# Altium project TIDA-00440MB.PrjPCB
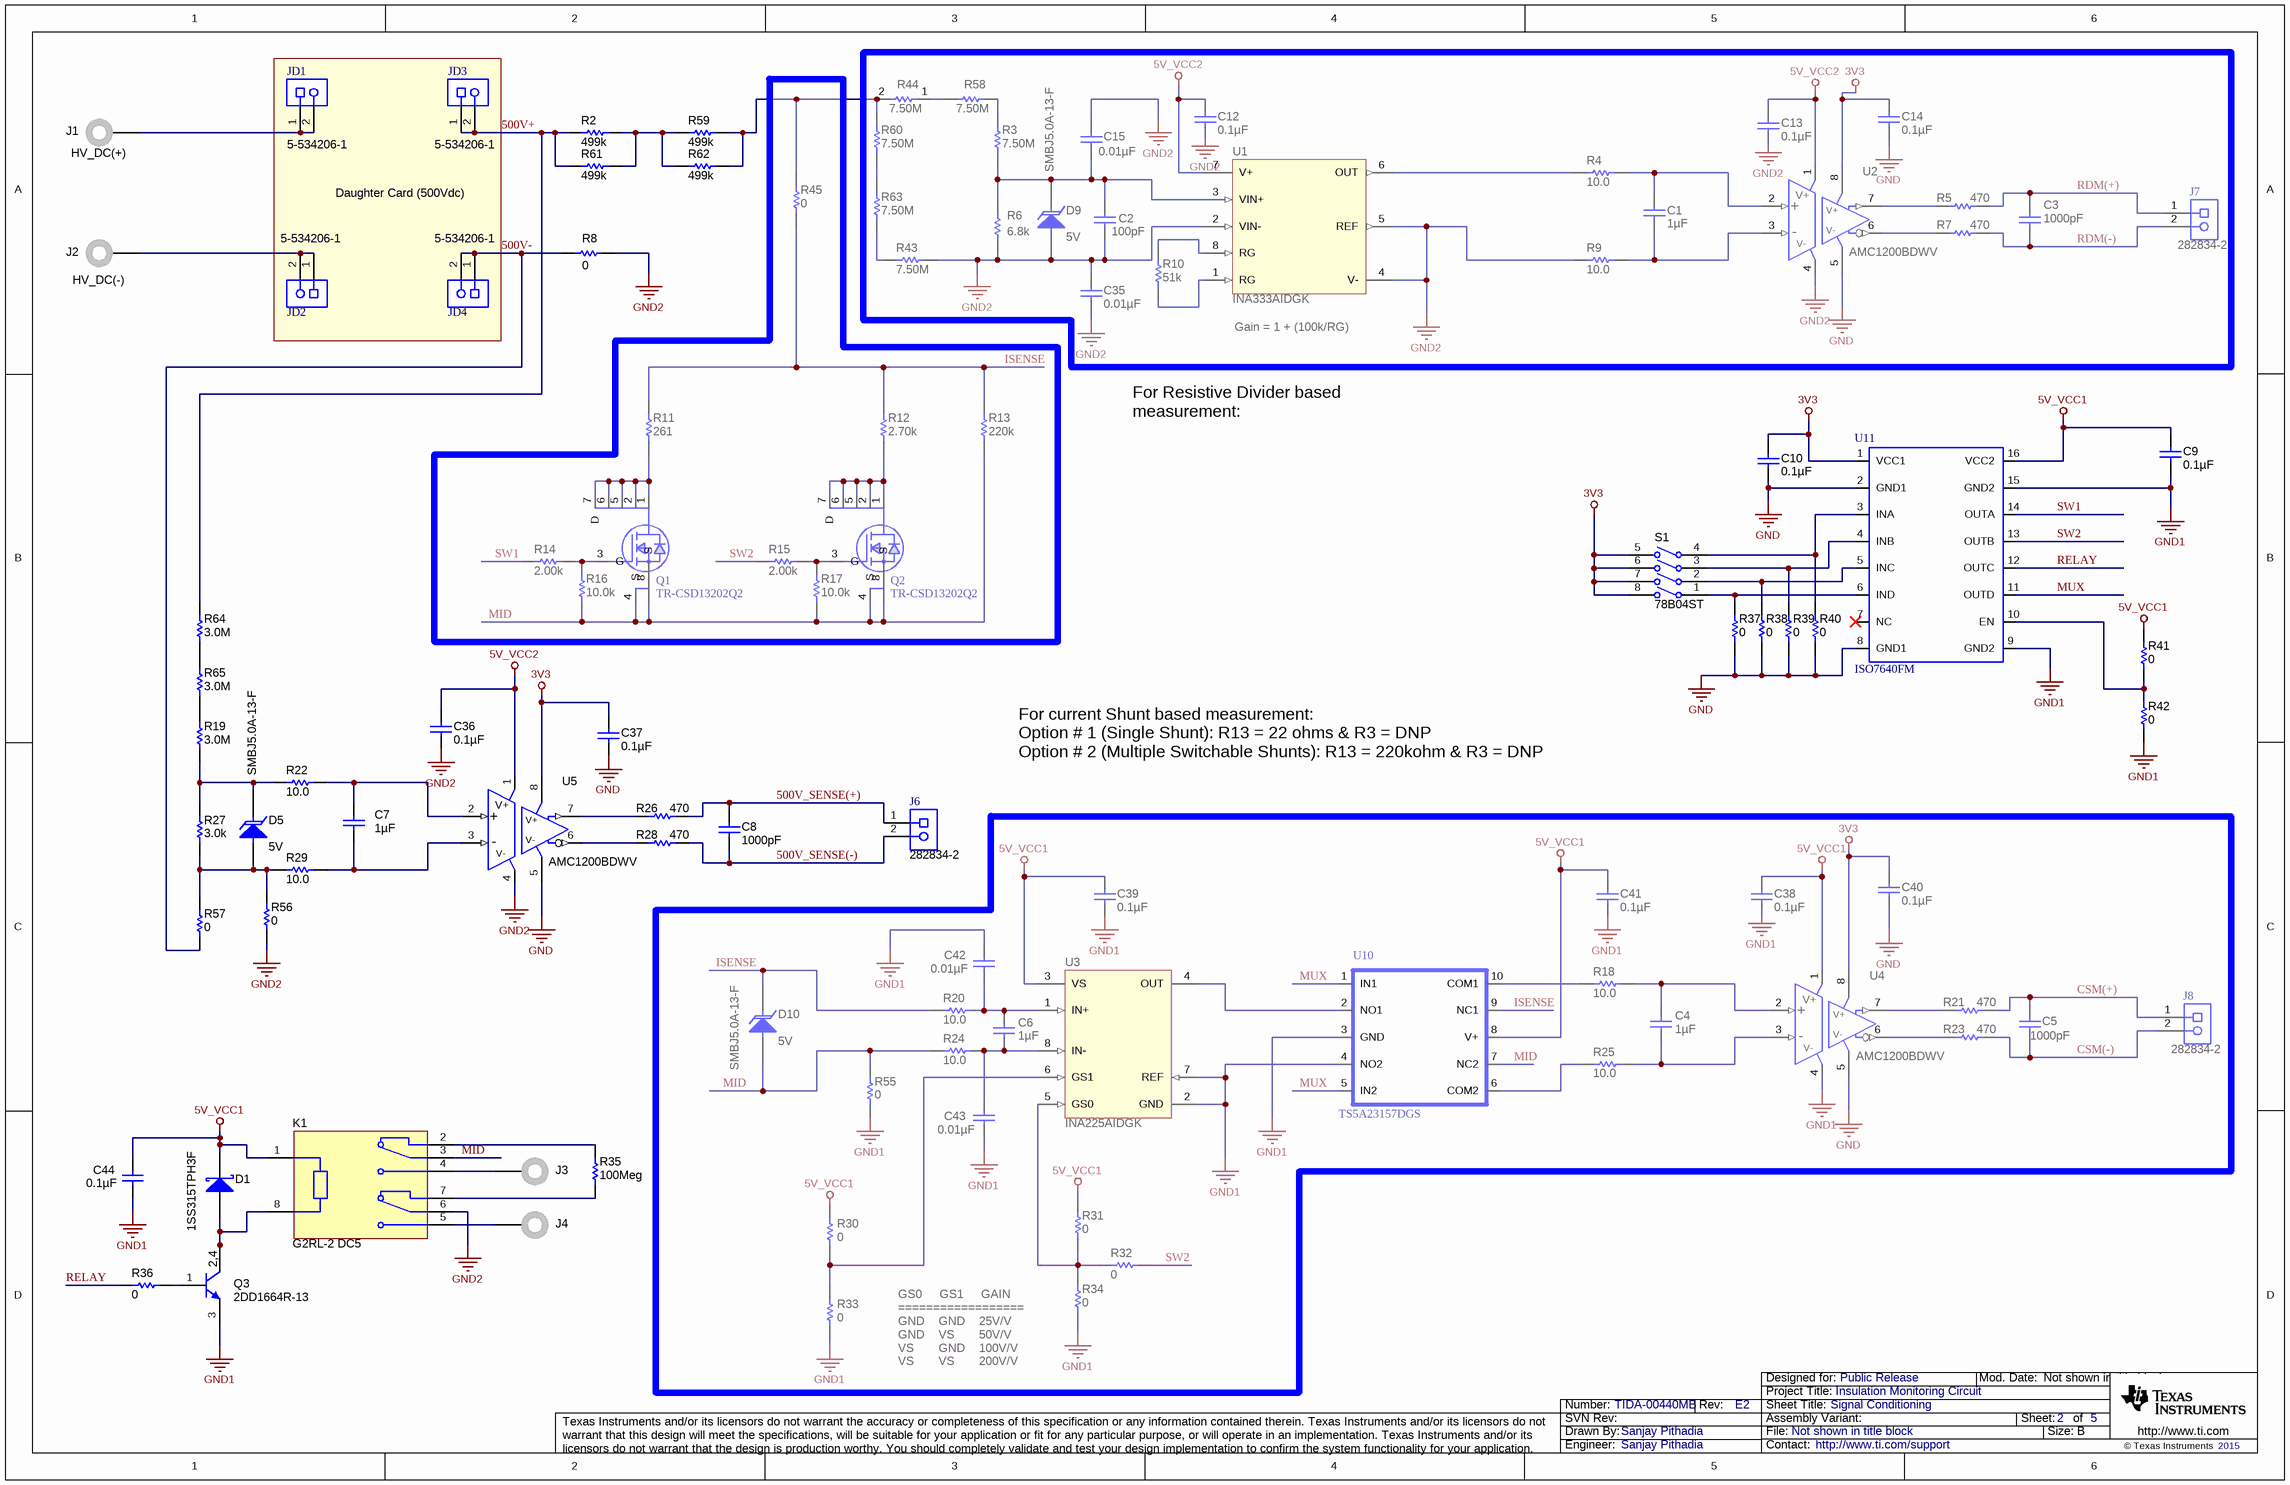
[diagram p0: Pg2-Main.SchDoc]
CopyrightYear: 2015; PCB_Layout: Manjunath M; PCB_Rev: E2; PRJ_Customer: Public Release; PRJ_Engineer: Sanjay Pithadia; PRJ_Number: TIDA-00440MB; PRJ_Title: Insulation Monitoring Circuit; SCH_Rev: E2; TechSupport: http://www.ti.com/support
4 sheets, 171 parts. Net scope: global (net labels, ports and power ports of the same name join across sheets).
Board file: TIDA-00440MB.PcbDoc
Sheets:
  Pg1-Cover.SchDoc
  Pg2-Main.SchDoc
  Pg3.SchDoc
  Pg4_Hardware_ANSI-B.SchDoc

## Sheet Pg1-Cover.SchDoc: Block Diagram
size 431 x 279 mm; Date: Not shown in title block; ApprovedBy: Not shown in title block; CheckedBy: Not shown in title block; Author: Not shown in title block; CompanyName: Not shown in title block; DrawnBy: Sanjay Pithadia; Engineer: Not shown in title block; Organization: Not shown in title block; Address1: Not shown in title block; Address2: Not shown in title block; Address3: Not shown in title block; Address4: Not shown in title block; DocumentNumber: 1; Revision: Use project parameter SCH_Rev; SheetNumber: 1; SheetTotal: 5; PageSetup: Record=PageOptions|CenterHorizontal=True|CenterVertical=True|PrintScale=1.00|XCorrection=1.00|YCorrection=1.00|PrintKind=0|BorderSize=5000000|LeftOffset=0|BottomOffset=0|Orientation=2|PaperLength=1000|PaperWidth=1000|Scale=100|PaperSource=15|PrintQuality=600|MediaType=1|DitherType=10|PaperKind=Letter|PrintScaleMode=1

## Sheet Pg2-Main.SchDoc: Signal Conditioning
size 431 x 279 mm; Date: Not shown in title block; ApprovedBy: Not shown in title block; CheckedBy: Not shown in title block; Author: Not shown in title block; CompanyName: Not shown in title block; DrawnBy: Sanjay Pithadia; Engineer: Not shown in title block; Organization: Not shown in title block; Address1: Not shown in title block; Address2: Not shown in title block; Address3: Not shown in title block; Address4: Not shown in title block; DocumentNumber: 2; Revision: Use project parameter SCH_Rev; SheetNumber: 2; SheetTotal: 5; PageSetup: Record=PageOptions|CenterHorizontal=True|CenterVertical=True|PrintScale=1.00|XCorrection=1.00|YCorrection=1.00|PrintKind=0|BorderSize=5000000|LeftOffset=0|BottomOffset=0|Orientation=2|PaperLength=1000|PaperWidth=1000|Scale=100|PaperSource=15|PrintQuality=600|MediaType=1|DitherType=10|PaperKind=Letter|PrintScaleMode=1

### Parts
C1  ValueDisplayed: 1µF  [0805_HV]  (hidden comment: 0805ZD105KAT2A)
C2  ValueDisplayed: 100pF  [0805_HV]  (hidden comment: 08055A101JAT2A)
C3  ValueDisplayed: 1000pF  [0805_HV]  (hidden comment: GRM216R71E102KA01D)
C4  ValueDisplayed: 1µF  [0805_HV]  (hidden comment: 0805ZD105KAT2A)
C5  ValueDisplayed: 1000pF  [0805_HV]  (hidden comment: GRM216R71E102KA01D)
C6  ValueDisplayed: 1µF  [0805_HV]  (hidden comment: 0805ZD105KAT2A)
C7  ValueDisplayed: 1µF  [0805_HV]  (hidden comment: 0805ZD105KAT2A)
C8  ValueDisplayed: 1000pF  [0805_HV]  (hidden comment: GRM216R71E102KA01D)
C9  ValueDisplayed: 0.1µF  [0805_HV]  (hidden comment: CC0805KRX7R7BB104)
C10  ValueDisplayed: 0.1µF  [0805_HV]  (hidden comment: CC0805KRX7R7BB104)
C12  ValueDisplayed: 0.1µF  [0805_HV]  (hidden comment: CC0805KRX7R7BB104)
C13  ValueDisplayed: 0.1µF  [0805_HV]  (hidden comment: CC0805KRX7R7BB104)
C14  ValueDisplayed: 0.1µF  [0805_HV]  (hidden comment: CC0805KRX7R7BB104)
C15  ValueDisplayed: 0.01µF  [0805_HV]  (hidden comment: C2012C0G1E103J)
C35  ValueDisplayed: 0.01µF  [0805_HV]  (hidden comment: C2012C0G1E103J)
C36  ValueDisplayed: 0.1µF  [0805_HV]  (hidden comment: CC0805KRX7R7BB104)
C37  ValueDisplayed: 0.1µF  [0805_HV]  (hidden comment: CC0805KRX7R7BB104)
C38  ValueDisplayed: 0.1µF  [0805_HV]  (hidden comment: CC0805KRX7R7BB104)
C39  ValueDisplayed: 0.1µF  [0805_HV]  (hidden comment: CC0805KRX7R7BB104)
C40  ValueDisplayed: 0.1µF  [0805_HV]  (hidden comment: CC0805KRX7R7BB104)
C41  ValueDisplayed: 0.1µF  [0805_HV]  (hidden comment: CC0805KRX7R7BB104)
C42  ValueDisplayed: 0.01µF  [0805_HV]  (hidden comment: C2012C0G1E103J)
C43  ValueDisplayed: 0.01µF  [0805_HV]  (hidden comment: C2012C0G1E103J)
C44  ValueDisplayed: 0.1µF  [0805_HV]  (hidden comment: CC0805KRX7R7BB104)
D1  1SS315TPH3F  [sod-323]
D5  SMBJ5.0A-13-F  value 5V  [SMB]
D9  SMBJ5.0A-13-F  value 5V  [SMB]
D10  SMBJ5.0A-13-F  value 5V  [SMB]
J1  3267  [Pomona_3267]  (value not drawn)
J2  3267  [Pomona_3267]  (value not drawn)
J3  3267  [Pomona_3267]  (value not drawn)
J4  3267  [Pomona_3267]  (value not drawn)
J6  282834-2  [TEC_282834-2]
J7  282834-2  [TEC_282834-2]
J8  282834-2  [TEC_282834-2]
JD1  5-534206-1  [CONN_534206-1]
JD2  5-534206-1  [CONN_534206-1]
JD3  5-534206-1  [CONN_534206-1]
JD4  5-534206-1  [CONN_534206-1]
K1  G2RL-2 DC5  [RELAY_G2RL-2_24]
Q1  TR-CSD13202Q2  [SON_2X2MM]
Q2  TR-CSD13202Q2  [SON_2X2MM]
Q3  2DD1664R-13  [SOT-89-3]
R2  ValueDisplayed: 499k  [2010]  (hidden comment: CRCW2010499KFKEF)
R3  ValueDisplayed: 7.50M  [1206]  (hidden comment: CRCW12067M50FKEA)
R4  ValueDisplayed: 10.0  [0805_HV]  (hidden comment: RT0805BRD0710RL)
R5  value 470  [0805_HV]  (hidden comment: CRCW0805470RFKEA)
R6  value 6.8k  [1206]  (hidden comment: CRCW12066K80JNEA)
R7  value 470  [0805_HV]  (hidden comment: CRCW0805470RFKEA)
R8  ValueDisplayed: 0  [2010]  (hidden comment: CRCW20100000Z0EF)
R9  ValueDisplayed: 10.0  [0805_HV]  (hidden comment: RT0805BRD0710RL)
R10  ValueDisplayed: 51k  [0805_HV]  (hidden comment: CRCW080551K0JNEA)
R11  ValueDisplayed: 261  [1206]  (hidden comment: RC1206FR-07261RL)
R12  ValueDisplayed: 2.70k  [1206]  (hidden comment: RC1206FR-072K7L)
R13  ValueDisplayed: 220k  [1206]  (hidden comment: RC1206FR-07220KL)
R14  ValueDisplayed: 2.00k  [0805_HV]  (hidden comment: CRCW08052K00FKEA)
R15  ValueDisplayed: 2.00k  [0805_HV]  (hidden comment: CRCW08052K00FKEA)
R16  ValueDisplayed: 10.0k  [0805_HV]  (hidden comment: CRCW080510K0FKEA)
R17  ValueDisplayed: 10.0k  [0805_HV]  (hidden comment: CRCW080510K0FKEA)
R18  ValueDisplayed: 10.0  [0805_HV]  (hidden comment: RT0805BRD0710RL)
R19  ValueDisplayed: 3.0M  [1206]  (hidden comment: CRCW12063M00JNEA)
R20  ValueDisplayed: 10.0  [0805_HV]  (hidden comment: RT0805BRD0710RL)
R21  value 470  [0805_HV]  (hidden comment: CRCW0805470RFKEA)
R22  ValueDisplayed: 10.0  [0805_HV]  (hidden comment: RT0805BRD0710RL)
R23  value 470  [0805_HV]  (hidden comment: CRCW0805470RFKEA)
R24  ValueDisplayed: 10.0  [0805_HV]  (hidden comment: RT0805BRD0710RL)
R25  ValueDisplayed: 10.0  [0805_HV]  (hidden comment: RT0805BRD0710RL)
R26  value 470  [0805_HV]  (hidden comment: CRCW0805470RFKEA)
R27  ValueDisplayed: 3.0k  [1206]  (hidden comment: CRCW12063K00JNEA)
R28  value 470  [0805_HV]  (hidden comment: CRCW0805470RFKEA)
R29  ValueDisplayed: 10.0  [0805_HV]  (hidden comment: RT0805BRD0710RL)
R30  value 0  [0805_HV]  (hidden comment: ERJ-6GEY0R00V)
R31  value 0  [0805_HV]  (hidden comment: ERJ-6GEY0R00V)
R32  value 0  [0805_HV]  (hidden comment: ERJ-6GEY0R00V)
R33  value 0  [0805_HV]  (hidden comment: ERJ-6GEY0R00V)
R34  value 0  [0805_HV]  (hidden comment: ERJ-6GEY0R00V)
R35  value 100Meg  [1206]  (hidden comment: CRCW120610M0JNEA)
R36  value 0  [0805_HV]  (hidden comment: ERJ-6GEY0R00V)
R37  value 0  [0805_HV]  (hidden comment: ERJ-6GEY0R00V)
R38  value 0  [0805_HV]  (hidden comment: ERJ-6GEY0R00V)
R39  value 0  [0805_HV]  (hidden comment: ERJ-6GEY0R00V)
R40  value 0  [0805_HV]  (hidden comment: ERJ-6GEY0R00V)
R41  value 0  [0805_HV]  (hidden comment: ERJ-6GEY0R00V)
R42  value 0  [0805_HV]  (hidden comment: ERJ-6GEY0R00V)
R43  ValueDisplayed: 7.50M  [1206]  (hidden comment: CRCW12067M50FKEA)
R44  ValueDisplayed: 7.50M  [1206]  (hidden comment: CRCW12067M50FKEA)
R45  ValueDisplayed: 0  [1206]  (hidden comment: CRCW12060000Z0EA)
R55  ValueDisplayed: 0  [0805_HV]  (hidden comment: CRCW08050000Z0EA)
R56  ValueDisplayed: 0  [0805_HV]  (hidden comment: CRCW08050000Z0EA)
R57  ValueDisplayed: 0  [1206]  (hidden comment: CRCW12060000Z0EA)
R58  ValueDisplayed: 7.50M  [1206]  (hidden comment: CRCW12067M50FKEA)
R59  ValueDisplayed: 499k  [2010]  (hidden comment: CRCW2010499KFKEF)
R60  ValueDisplayed: 7.50M  [1206]  (hidden comment: CRCW12067M50FKEA)
R61  ValueDisplayed: 499k  [2010]  (hidden comment: CRCW2010499KFKEF)
R62  ValueDisplayed: 499k  [2010]  (hidden comment: CRCW2010499KFKEF)
R63  ValueDisplayed: 7.50M  [1206]  (hidden comment: CRCW12067M50FKEA)
R64  ValueDisplayed: 3.0M  [1206]  (hidden comment: CRCW12063M00JNEA)
R65  ValueDisplayed: 3.0M  [1206]  (hidden comment: CRCW12063M00JNEA)
S1  78B04ST  [SW_78B04ST]
U1  INA333AIDGK  [DGK0008A_N]
U2  AMC1200BDWV  [DWV0008A]
U3  INA225AIDGK  [DGK0008A_N]
U4  AMC1200BDWV  [DWV0008A]
U5  AMC1200BDWV  [DWV0008A]
U10  TS5A23157DGS  [DGS_10P]
U11  ISO7640FM  [DW16]

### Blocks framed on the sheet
Gain = 1 + (100k/RG): C1-C3 C12-C15 C35 D9 J7 R3-R7 R9 R10 R43 R44 R58 R60 R63 U1 U2
Daughter Card (500Vdc): JD1-JD4

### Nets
3V3: C10.1 C14.1 C37.1 C40.1 S1.5(B4) S1.6(B3) S1.7(B2) S1.8(B1) U2.8(VDD2) U4.8(VDD2) U5.8(VDD2) U11.1(VCC1)
5V_VCC1: C9.1 C38.1 C39.1 C41.1 C44.1 D1.1(K) K1.1 R30.1 R31.1 R41.1 U3.3(VS) U4.1(VDD1) U10.8(V+) U11.16(VCC2)
5V_VCC2: C12.1 C13.1 C36.1 U1.7(V+) U2.1(VDD1) U5.1(VDD1)
GND: C10.2 C14.2 C37.2 C40.2 R37.2 R38.2 R39.2 R40.2 U2.5(GND2) U4.5(GND2) U5.5(GND2) U11.2(GND1) U11.8(GND1)
GND1: C9.2 C38.2 C39.2 C41.2 C42.1 C43.2 C44.2 Q3.3(E) R33.1 R34.1 R42.1 R55.1 U3.2(GND) U3.7(REF) U4.4(GND1) U10.3(GND) U10.4(NO2) U11.9(GND2) U11.15(GND2)
GND2: C2.2 C12.2 C13.2 C15.1 C35.1 C35.2 C36.2 D9.2(A) K1.6 R6.1 R8.2 R9.1 R43.1 R56.1 U1.2(VIN-) U1.4(V-) U1.5(REF) U2.4(GND1) U5.4(GND1)
500V+: JD3.1 JD3.2 R2.1 R61.1 R64.2
500V-: JD4.1 JD4.2 R8.1 R57.1
500V_SENSE(+): C8.1 J6.1 R26.2
500V_SENSE(-): C8.2 J6.2 R28.2
CSM(+): C5.1 J8.1 R21.2
CSM(-): C5.2 J8.2 R23.2
ISENSE: D10.1(K) R11.2 R12.2 R13.2 R20.1 R45.1 U10.9(NC1)
MID: D10.2(A) K1.3 Q1.4(S) Q1.8(S) Q2.4(S) Q2.8(S) R13.1 R16.1 R17.1 R24.1 R55.2 U10.7(NC2)
MUX: U10.1(IN1) U10.5(IN2) U11.11(OUTD)
RDM(+): C3.1 J7.1 R5.2
RDM(-): C3.2 J7.2 R7.2
RELAY: R36.2 U11.12(OUTC)
SW1: R14.1 U11.14(OUTA)
SW2: R15.1 R32.1 U11.13(OUTB)
NetC1_1: C1.1 R4.2 U2.2(VINP)
NetC1_2: C1.2 R9.2 U2.3(VINN)
NetC2_1: C2.1 C15.2 D9.1(K) R3.1 R6.2 U1.3(VIN+)
NetC4_1: C4.1 R18.2 U4.2(VINP)
NetC4_2: C4.2 R25.2 U4.3(VINN)
NetC6_1: C6.1 C42.2 R20.2 U3.1(IN+)
NetC6_2: C6.2 C43.1 R24.2 U3.8(IN-)
NetC7_1: C7.1 R22.2 U5.2(VINP)
NetC7_2: C7.2 R29.2 U5.3(VINN)
NetD1_2: D1.2(A) K1.8 Q3.2(C) Q3.4(C)
NetD5_1: D5.1(K) R19.1 R22.1 R27.2
NetD5_2: D5.2(A) R27.1 R29.1 R56.2 R57.2
NetJ1_1: J1.1 JD1.1 JD1.2
NetJ2_1: J2.1 JD2.1 JD2.2
NetJ3_1: J3.1 K1.4
NetJ4_1: J4.1 K1.5
NetK1_2: K1.2 R35.2
NetK1_7: K1.7 R35.1
NetQ1_1: Q1.1 Q1.2 Q1.5 Q1.6 Q1.7(D) R11.1
NetQ1_3: Q1.3(G) R14.2 R16.2
NetQ2_1: Q2.1 Q2.2 Q2.5 Q2.6 Q2.7(D) R12.1
NetQ2_3: Q2.3(G) R15.2 R17.2
NetQ3_1: Q3.1(B) R36.1
NetR2_2: R2.2 R59.1 R61.2 R62.1
NetR3_2: R3.2 R58.1
NetR4_1: R4.1 U1.6(OUT)
NetR5_1: R5.1 U2.7(VOUTP)
NetR7_1: R7.1 U2.6(VOUTN)
NetR10_1: R10.1 U1.1(RG)
NetR10_2: R10.2 U1.8(RG)
NetR18_1: R18.1 U10.10(COM1)
NetR19_2: R19.2 R65.1
NetR21_1: R21.1 U4.7(VOUTP)
NetR23_1: R23.1 U4.6(VOUTN)
NetR25_1: R25.1 U10.6(COM2)
NetR26_1: R26.1 U5.7(VOUTP)
NetR28_1: R28.1 U5.6(VOUTN)
NetR30_2: R30.2 R33.2 U3.6(GS1)
NetR31_2: R31.2 R32.2 R34.2 U3.5(GS0)
NetR37_1: R37.1 S1.1(A1) U11.6(IND)
NetR38_1: R38.1 S1.2(A2) U11.5(INC)
NetR39_1: R39.1 S1.3(A3) U11.4(INB)
NetR40_1: R40.1 S1.4(A4) U11.3(INA)
NetR41_2: R41.2 R42.2 U11.10(EN)
NetR43_2: R43.2 R63.1
NetR44_1: R44.1 R58.2
NetR44_2: R44.2 R45.2 R59.2 R60.2 R62.2
NetR60_1: R60.1 R63.2
NetR64_1: R64.1 R65.2
NetU3_4: U3.4(OUT) U10.2(NO1)

Not connected (* = marked no-connect by the designer): U11 7(NC)*

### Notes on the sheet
- (near J1) HV_DC(+)
- (near J2) HV_DC(-)
- For Resistive Divider based measurement:
  R13 = 0 ohm, R43 = DNP
- For current Shunt based measurement:
  Option # 1 (Single Shunt): R13 = 22 ohms & R3 = DNP
  Option # 2 (Multiple Switchable Shunts): R13 = 220kohm & R3 = DNP
- GS0     GS1     GAIN
  ==================
  GND    GND    25V/V
  GND    VS       50V/V
  VS       GND    100V/V
  VS       VS       200V/V

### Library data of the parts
C1 C4 C6 C7 = 0805ZD105KAT2A: CAP, CERM, 1uF, 10V, +/-10%, X5R, 0805; Manufacturer: AVX; Polarized: N; CompType: Capacitor; U/M: EA; Cap_F: 0.000001; Tolerance_%: 10; ESR_Ohm: 0.012; Value1: 0.012 ohm; TaMin_C: -55; TaMax_C: 85; Cap_Case: 0805
C2 = 08055A101JAT2A: CAP, CERM, 100pF, 50V, +/-5%, C0G/NP0, 0805; Manufacturer: AVX; Polarized: N; CompType: Capacitor; U/M: EA; Cap_F: 0.0000000001; Tolerance_%: 5; ESR_Ohm: 0.356; Value1: 0.356 ohm; VDC_V: 50; TaMin_C: -55; TaMax_C: 125; Cap_Case: 0805
C3 C5 C8 = GRM216R71E102KA01D: CAP, CERM, 1000 pF, 25 V, +/- 10%, X7R, 0805; Manufacturer: MuRata; Polarized: N; CompType: Capacitor; Value: 1000pF; U/M: EA; Cap_F: 0.000000001; Tolerance_%: 10; Value1: Unknown; VDC_V: 25; Value2: 25V; TaMin_C: -55; TaMax_C: 125; Cap_Case: 0805
C9 C10 C12-C14 C36-C41 C44 = CC0805KRX7R7BB104: CAP, CERM, 0.1 µF, 16 V, +/- 10%, X7R, 0805; Manufacturer: Yageo America; Polarized: N; CompType: Capacitor; Value: 0.1uF; U/M: EA; Cap_F: 0.0000001; Tolerance_%: 10; Value1: Unknown; VDC_V: 16; Value2: 16V; TaMin_C: -55; TaMax_C: 125; Cap_Case: 0805
C15 C35 C42 C43 = C2012C0G1E103J: CAP, CERM, 0.01 µF, 25 V, +/- 5%, C0G/NP0, 0805; Manufacturer: TDK; Polarized: N; CompType: Capacitor; Value: 0.01uF; U/M: EA; Cap_F: 0.00000001; Tolerance_%: 5; ESR_ohm: 0.03; Value1: 0.03 ohm; VDC_V: 25; Value2: 25V; TaMin_C: -55; TaMax_C: 125; Cap_Case: 0805
D1 = 1SS315TPH3F: Diode, Schottky, 5 V, 0.03 A, SOD-323; Manufacturer: Toshiba; U/M: EA; Vf_V: 0.38; Value: 5V; Value1: 0.03A; Value2: 0.38V; Io_A: 0.03; Vr_V: 5; TJmax_C: 125
D5 D9 D10 = SMBJ5.0A-13-F: Diode, TVS, Uni, 5 V, 600 W, SMB; Manufacturer: Diodes Inc.; U/M: EA; Power_W: 5; Value1: 5W
J1-J4 = 3267: Standard Banana Jack, Uninsulated; Manufacturer: Pomona Electronics; SymbolCreator: a0412235; CompType: Connector; U/M: EA
J6-J8 = 282834-2: Terminal Block, 2x1, 2.54mm, TH; Manufacturer: TE Connectivity; SymbolCreator: a0412235; U/M: EA
JD1-JD4 = 5-534206-1: Connector, Receptacle, 100mil, 2x1, Gold plated, TH; Manufacturer: TE Connectivity; SymbolCreator: a0412235; U/M: EA
K1 = G2RL-2 DC5: Relay, DPDT, 8A, 5VDC, TH; Manufacturer: Omron Electronic Components; SymbolCreator: a0411947; Coil Current: 80mA; Coil Power: 400mW; Coil Resistance: 62.5 ohm; Coil Type: Non Latching; Turn Off Voltage (Min): 0.5VDC; Turn On Voltage (Max): 3.5VDC; Time Operate (s): 0.015; Time Release (s): 0.005
Q1 Q2 = TR-CSD13202Q2: Trans, Nch, 12V, 20A, 10 mOhm; Manufacturer: TI; Alternate Manufacturer: None; SymbolVersion: 04/09/20121 2:30:37; Area: 27300
Q3 = 2DD1664R-13, Diodes Inc.: Transistor, NPN, 32 V, 1 A, SOT-89; SymbolCreator: a0412235; PNP: 0; NPN: 1; Vceo_V: 32; Vcesat1_V: 0.4; Value: 32 V; Value1: 1 A; HfeMax: 390; TaMin_C: -55; TaMax_C: 150; CompType: BJT; U/M: EA
R2 R59 R61 R62 = CRCW2010499KFKEF: RES, 499 k, 1%, 0.75 W, 2010; Manufacturer: Vishay-Dale; CompType: Resistor; Value: 499k; Res_ohm: 499000; Tolerance_%: 1; Power_W: 0.75; Value2: 0.75W; VDC_V: 400; TempCo: 100 ppm/C; EIA_Code: E96; U/M: EA
R3 R43 R44 R58 R60 R63 = CRCW12067M50FKEA: RES, 7.50 M, 1%, 0.25 W, 1206; Manufacturer: Vishay-Dale; CompType: Resistor; Value: 7.50Meg; Res_ohm: 7500000; Value_Code: 7M50; Tolerance_%: 1; Power_W: 0.25; Value2: 0.25W; VDC_V: 200; TempCo: 100 ppm/C; EIA_Code: E96; U/M: EA
R4 R9 R18 R20 R22 R24 R25 R29 = RT0805BRD0710RL: RES, 10.0, 0.1%, 0.125 W, 0805; Manufacturer: Yageo America; CompType: Resistor; Value: 10.0; Res_ohm: 10; Value_Code: 10R0; Tolerance_%: 0.1; Power_W: 0.125; Value2: 0.125W; VDC_V: 150; TempCo: 25 ppm/C; EIA_Code: E192; U/M: EA
R5 R7 R21 R23 R26 R28 = CRCW0805470RFKEA: RES, 470 ohm, 1%, 0.125W, 0805; Manufacturer: Vishay-Dale; CompType: Resistor; Value_Code: 470R; Tolerance_%: 1; Power_W: 0.125; VDC_V: 150; TempCo: 100 ppm/C; U/M: EA
R6 = CRCW12066K80JNEA: RES, 6.8k ohm, 5%, 0.25W, 1206; Manufacturer: Vishay-Dale; CompType: Resistor; Res_ohm: 6800; Value_Code: 6k80; Tolerance_%: 5; Power_W: 0.25; VDC_V: 200; TempCo: 200 ppm/C; EIA_Code: E24; U/M: EA
R8 = CRCW20100000Z0EF: RES, 0, 5%, 0.75 W, 2010; Manufacturer: Vishay-Dale; CompType: Resistor; Value: 0; Value_Code: 0000; Tolerance_%: 5; Power_W: 0.75; Value2: 0.75W; TempCo: ppm/C; EIA_Code: E24; U/M: EA
R10 = CRCW080551K0JNEA: RES, 51 k, 5%, 0.125 W, 0805; Manufacturer: Vishay-Dale; CompType: Resistor; Value: 51k; Res_ohm: 51000; Value_Code: 51k0; Tolerance_%: 5; Power_W: 0.125; Value2: 0.125W; VDC_V: 150; TempCo: 200 ppm/C; EIA_Code: E24; U/M: EA
R11 = RC1206FR-07261RL: RES, 261, 1%, 0.25 W, 1206; Manufacturer: Yageo America; CompType: Resistor; Value: 261; Value_Code: 261R; Tolerance_%: 1; Power_W: 0.25; Value2: 0.25W; VDC_V: 200; TempCo: 100 ppm/C; EIA_Code: E96; U/M: EA
R12 = RC1206FR-072K7L: RES, 2.70 k, 1%, 0.25 W, 1206; Manufacturer: Yageo America; CompType: Resistor; Value: 2.70k; Res_ohm: 2700; Value_Code: 2k70; Tolerance_%: 1; Power_W: 0.25; Value2: 0.25W; VDC_V: 200; TempCo: 100 ppm/C; U/M: EA
R13 = RC1206FR-07220KL: RES, 220 k, 1%, 0.25 W, 1206; Manufacturer: Yageo America; CompType: Resistor; Value: 220k; Res_ohm: 220000; Tolerance_%: 1; Power_W: 0.25; Value2: 0.25W; VDC_V: 200; TempCo: 100 ppm/C; U/M: EA
R14 R15 = CRCW08052K00FKEA: RES, 2.00 k, 1%, 0.125 W, 0805; Manufacturer: Vishay-Dale; CompType: Resistor; Value: 2.00k; Res_ohm: 2000; Value_Code: 2k00; Tolerance_%: 1; Power_W: 0.125; Value2: 0.125W; VDC_V: 150; TempCo: 100 ppm/C; EIA_Code: E96; U/M: EA
R16 R17 = CRCW080510K0FKEA: RES, 10.0 k, 1%, 0.125 W, 0805; Manufacturer: Vishay-Dale; CompType: Resistor; Value: 10.0k; Res_ohm: 10000; Value_Code: 10k0; Tolerance_%: 1; Power_W: 0.125; Value2: 0.125W; VDC_V: 150; TempCo: 100 ppm/C; EIA_Code: E96; U/M: EA
R19 R64 R65 = CRCW12063M00JNEA: RES, 3.0 M, 5%, 0.25 W, 1206; Manufacturer: Vishay-Dale; CompType: Resistor; Value: 3.0Meg; Res_ohm: 3000000; Value_Code: 3M00; Tolerance_%: 5; Power_W: 0.25; Value2: 0.25W; VDC_V: 200; TempCo: 200 ppm/C; EIA_Code: E24; U/M: EA
R27 = CRCW12063K00JNEA: RES, 3.0 k, 5%, 0.25 W, 1206; Manufacturer: Vishay-Dale; CompType: Resistor; Value: 3.0k; Res_ohm: 3000; Value_Code: 3k00; Tolerance_%: 5; Power_W: 0.25; Value2: 0.25W; VDC_V: 200; TempCo: 200 ppm/C; EIA_Code: E24; U/M: EA
R30-R34 R36-R42 = ERJ-6GEY0R00V: RES, 0 ohm, 5%, 0.125W, 0805; Manufacturer: Panasonic; CompType: Resistor; Value_Code: 0000; Tolerance_%: 5; Power_W: 0.125; VDC_V: 150; TempCo: 600 ppm/C; EIA_Code: E24; U/M: EA
R35 = CRCW120610M0JNEA: RES, 10Meg ohm, 5%, 0.25W, 1206; Manufacturer: Vishay-Dale; CompType: Resistor; Res_ohm: 10000000; Value_Code: 10M0; Tolerance_%: 5; Power_W: 0.25; VDC_V: 200; TempCo: 200 ppm/C; EIA_Code: E24; U/M: EA
R45 R57 = CRCW12060000Z0EA: RES, 0, 5%, 0.25 W, 1206; Manufacturer: Vishay-Dale; CompType: Resistor; Value: 0; Value_Code: 0000; Tolerance_%: 5; Power_W: 0.25; Value2: 0.25W; VDC_V: 200; TempCo: 200 ppm/C; EIA_Code: E24; U/M: EA
R55 R56 = CRCW08050000Z0EA: RES, 0, 5%, 0.125 W, 0805; Manufacturer: Vishay-Dale; CompType: Resistor; Value: 0; Value_Code: 0000; Tolerance_%: 5; Power_W: 0.125; Value2: 0.125W; VDC_V: 150; TempCo: 200 ppm/C; EIA_Code: E24; U/M: EA
S1 = 78B04ST: DIP Switch, SPST 4Pos, Slide, TH; Manufacturer: Grayhill; SymbolCreator: a0412235; VDC_V: 30; SwitchFunction: Off-On; PositionCount: 4; CurrentRating_mA: 150
U1 = INA333AIDGK: Micro-Power (50mA), Zerø-Drift, Rail-to-Rail Out Instrumentation Amplifier; Alternate Manufacturer: None; Manufacturer: Texas Instruments; SymbolCreator: a0799628; CompType: IC; U/M: EA
U2 U4 U5 = AMC1200BDWV: Fully-Differential Isolation Amplifier, DWV0008A; Alternate Manufacturer: None; Manufacturer: Texas Instruments; SymbolCreator: a0411947; CompType: IC; U/M: EA
U3 = INA225AIDGK: 36-V, Programmable-Gain, Voltage-Output, Bidirectional, Zero-Drift Series, Current-Shunt Monitor, DGK0008A; Alternate Manufacturer: None; Manufacturer: Texas Instruments; SymbolCreator: a0799628; CompType: IC; U/M: EA
U10 = TS5A23157DGS: IC, Dual 10 Ohms SPDT Analog Switch; Manufacturer: TI; Alternate Manufacturer: None; Area: 44.100
U11 = ISO7640FM: IC,Low Power Triple and Quad Channels Digital Isolators; Manufacturer: TI; Alternate Manufacturer: None; Area: 215160

## Sheet Pg3.SchDoc: Power Supply
size 431 x 279 mm; Date: Not shown in title block; ApprovedBy: Not shown in title block; CheckedBy: Not shown in title block; Author: Not shown in title block; CompanyName: Not shown in title block; DrawnBy: Sanjay Pithadia; Engineer: Not shown in title block; Organization: Not shown in title block; Address1: Not shown in title block; Address2: Not shown in title block; Address3: Not shown in title block; Address4: Not shown in title block; DocumentNumber: 3; Revision: Use project parameter SCH_Rev; SheetNumber: 3; SheetTotal: 5; PageSetup: Record=PageOptions|CenterHorizontal=True|CenterVertical=True|PrintScale=1.00|XCorrection=1.00|YCorrection=1.00|PrintKind=0|BorderSize=5000000|LeftOffset=0|BottomOffset=0|Orientation=2|PaperLength=1000|PaperWidth=1000|Scale=100|PaperSource=15|PrintQuality=600|MediaType=1|DitherType=10|PaperKind=Letter|PrintScaleMode=1
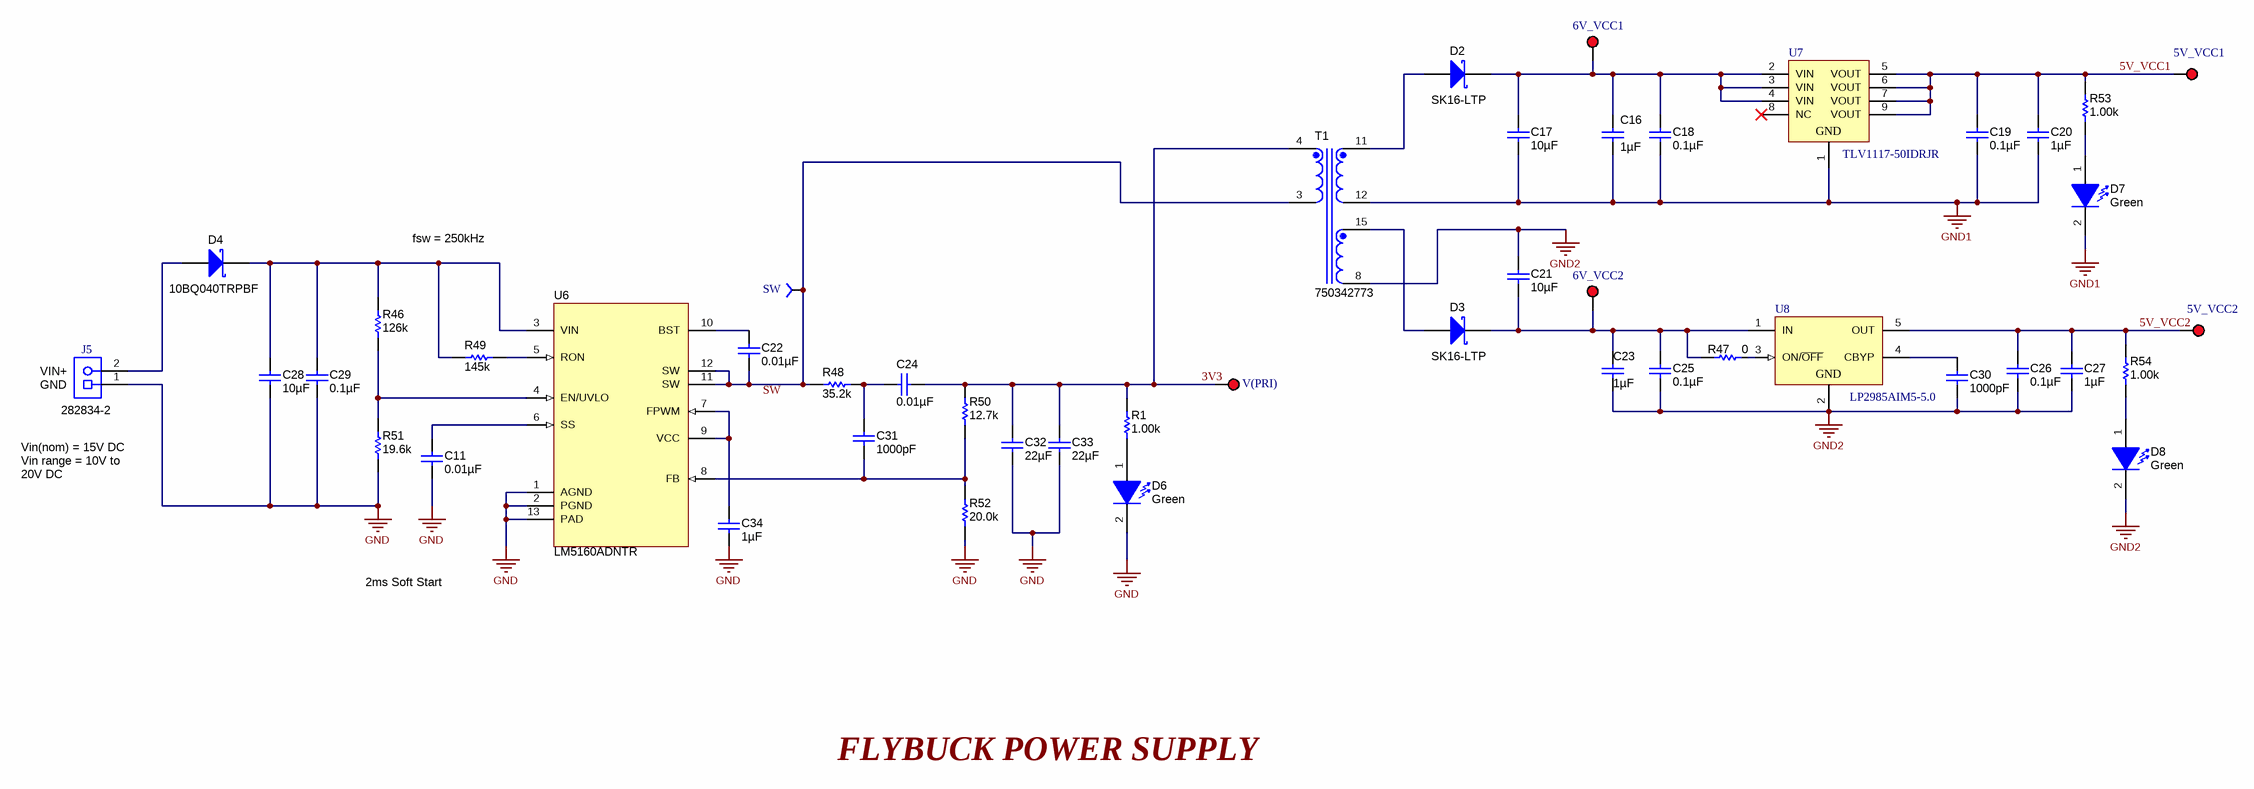
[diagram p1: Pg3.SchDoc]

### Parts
5V_VCC1  5000  [Keystone5000]  (value not drawn)
5V_VCC2  5000  [Keystone5000]  (value not drawn)
6V_VCC1  5000  [Keystone5000]  (value not drawn)
6V_VCC2  5000  [Keystone5000]  (value not drawn)
C11  ValueDisplayed: 0.01µF  [0805_HV]  (hidden comment: C2012C0G1E103J)
C16  ValueDisplayed: 1µF  [0805_HV]  (hidden comment: GRM21BR71A105KA01L)
C17  ValueDisplayed: 10µF  [1210]  (hidden comment: GRM32DR71A106KA01L)
C18  ValueDisplayed: 0.1µF  [0805_HV]  (hidden comment: CC0805KRX7R7BB104)
C19  ValueDisplayed: 0.1µF  [0805_HV]  (hidden comment: CC0805KRX7R7BB104)
C20  ValueDisplayed: 1µF  [0805_HV]  (hidden comment: GRM21BR71A105KA01L)
C21  ValueDisplayed: 10µF  [1210]  (hidden comment: GRM32DR71A106KA01L)
C22  ValueDisplayed: 0.01µF  [0805_HV]  (hidden comment: C2012C0G1E103J)
C23  ValueDisplayed: 1µF  [0805_HV]  (hidden comment: GRM21BR71A105KA01L)
C24  ValueDisplayed: 0.01µF  [0805_HV]  (hidden comment: C2012C0G1E103J)
C25  ValueDisplayed: 0.1µF  [0805_HV]  (hidden comment: CC0805KRX7R7BB104)
C26  ValueDisplayed: 0.1µF  [0805_HV]  (hidden comment: CC0805KRX7R7BB104)
C27  ValueDisplayed: 1µF  [0805_HV]  (hidden comment: GRM21BR71A105KA01L)
C28  ValueDisplayed: 10µF  [1206_190]  (hidden comment: GMK316BJ106KL-T)
C29  ValueDisplayed: 0.1µF  [0805_HV]  (hidden comment: 08053C104KAT2A)
C30  ValueDisplayed: 1000pF  [0805_HV]  (hidden comment: GRM216R71E102KA01D)
C31  ValueDisplayed: 1000pF  [0805_HV]  (hidden comment: GRM216R71E102KA01D)
C32  ValueDisplayed: 22µF  [0805_HV]  (hidden comment: C2012JB1V226M125AC)
C33  ValueDisplayed: 22µF  [0805_HV]  (hidden comment: C2012JB1V226M125AC)
C34  ValueDisplayed: 1µF  [0805_HV]  (hidden comment: GMK212B7105KG-T)
D2  SK16-LTP  [SMB]
D3  SK16-LTP  [SMB]
D4  10BQ040TRPBF  [SMB]
D6  value Green  [LG L29K_GREEN]  (hidden comment: LG L29K-G2J1-24-Z)
D7  value Green  [LG L29K_GREEN]  (hidden comment: LG L29K-G2J1-24-Z)
D8  value Green  [LG L29K_GREEN]  (hidden comment: LG L29K-G2J1-24-Z)
J5  282834-2  [TEC_282834-2]
R1  ValueDisplayed: 1.00k  [0805_HV]  (hidden comment: CRCW08051K00FKEA)
R46  value 126k  [0805_HV]  (hidden comment: RT0805BRD07126KL)
R47  value 0  [0805_HV]  (hidden comment: ERJ-6GEY0R00V)
R48  ValueDisplayed: 35.2k  [0805_HV]  (hidden comment: RT0805BRD0735K2L)
R49  ValueDisplayed: 145k  [0805_HV]  (hidden comment: RT0805BRD07145KL)
R50  ValueDisplayed: 12.7k  [0805_HV]  (hidden comment: CRCW080512K7FKEA)
R51  ValueDisplayed: 19.6k  [0805_HV]  (hidden comment: CRCW080519K6FKEA)
R52  ValueDisplayed: 20.0k  [0805_HV]  (hidden comment: CRCW080520K0FKEA)
R53  ValueDisplayed: 1.00k  [0805_HV]  (hidden comment: CRCW08051K00FKEA)
R54  ValueDisplayed: 1.00k  [0805_HV]  (hidden comment: CRCW08051K00FKEA)
SW  TP-032_RND  [TP-032_RND]  (value not drawn)
T1  750342773  [Wurth_750342773]
U6  LM5160ADNTR  [DNT0012B]
U7  TLV1117-50IDRJR  [DRJ0008A]
U8  LP2985AIM5-5.0  [MF05A_N]
V(PRI)  5000  [Keystone5000]  (value not drawn)

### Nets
3V3: C24.1 C32.1 C33.1 R1.1 R50.2 T1.4 V(PRI).1
5V_VCC1: 5V_VCC1.1 C19.1 C20.1 R53.1 U7.5(VOUT) U7.6(VOUT) U7.7(VOUT) U7.9(VOUT)
5V_VCC2: 5V_VCC2.1 C26.1 C27.2 R54.1 U8.5(OUT)
GND: C11.2 C28.2 C29.2 C32.2 C33.2 C34.2 D6.2(K) J5.1 R51.1 R52.1 U6.1(AGND) U6.2(PGND) U6.13(PAD)
GND1: C16.2 C17.2 C18.2 C19.2 C20.2 D7.2(K) T1.12 U7.1(ADJ/GND)
GND2: C21.1 C23.2 C25.2 C26.2 C27.1 C30.2 D8.2(K) T1.8 U8.2(GND)
Net6V_VCC1_1: 6V_VCC1.1 C16.1 C17.1 C18.1 D2.1(K) U7.2(VIN) U7.3(VIN) U7.4(VIN)
Net6V_VCC2_1: 6V_VCC2.1 C21.2 C23.1 C25.1 D3.1(K) R47.2 U8.1(IN)
NetC11_1: C11.1 U6.6(SS)
NetC22_1: C22.1 U6.10(BST)
NetC22_2: C22.2 R48.1 SW.1 T1.3 U6.11(SW) U6.12(SW)
NetC24_2: C24.2 C31.2 R48.2
NetC28_1: C28.1 C29.1 D4.1(K) R46.2 R49.1 U6.3(VIN)
NetC30_1: C30.1 U8.4(CBYP)
NetC31_1: C31.1 R50.1 R52.2 U6.8(FB)
NetC34_1: C34.1 U6.7(FPWM) U6.9(VCC)
NetD2_2: D2.2(A) T1.11
NetD3_2: D3.2(A) T1.15
NetD4_2: D4.2(A) J5.2
NetD6_1: D6.1(A) R1.2
NetD7_1: D7.1(A) R53.2
NetD8_1: D8.1(A) R54.2
NetR46_1: R46.1 R51.2 U6.4(EN/UVLO)
NetR47_1: R47.1 U8.3(ON/~{OFF})
NetR49_2: R49.2 U6.5(RON)

Not connected (* = marked no-connect by the designer): U7 8(NC)*

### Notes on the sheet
- fsw = 250kHz
- (near J5) VIN+
- (near J5) GND
- Vin(nom) = 15V DC
  Vin range = 10V to 20V DC
- 2ms Soft Start
- FLYBUCK POWER SUPPLY
- Labels drawn without touching a wire or pin: SW

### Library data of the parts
5V_VCC1 5V_VCC2 6V_VCC1 6V_VCC2 V(PRI) = 5000: Test Point, Miniature, Red, TH; Manufacturer: Keystone; CompType: Test Point Loop; U/M: EA
C11 C22 C24 = C2012C0G1E103J: as C15 on sheet Pg2-Main
C16 C20 C23 C27 = GRM21BR71A105KA01L: CAP, CERM, 1uF, 10V, +/-10%, X7R, 0805; Manufacturer: MuRata; Polarized: N; CompType: Capacitor; U/M: EA; Cap_F: 0.000001; Tolerance_%: 10; ESR_Ohm: 0.007; Value1: 0.007 ohm; TaMin_C: -55; TaMax_C: 125; Cap_Case: 0805
C17 C21 = GRM32DR71A106KA01L: CAP, CERM, 10 µF, 10 V, +/- 10%, X5R, 1210; Manufacturer: MuRata; Polarized: N; CompType: Capacitor; Value: 10uF; U/M: EA; Cap_F: 0.00001; Tolerance_%: 10; Value1: Unknown; Value2: 10V; TaMin_C: -55; TaMax_C: 85
C18 C19 C25 C26 = CC0805KRX7R7BB104: as C9 on sheet Pg2-Main
C28 = GMK316BJ106KL-T: CAP, CERM, 10 µF, 35 V, +/- 10%, X5R, 1206_190; Manufacturer: Taiyo Yuden; Polarized: N; CompType: Capacitor; Value: 10uF; U/M: EA; Cap_F: 0.00001; Tolerance_%: 10; Value1: Unknown; VDC_V: 35; Value2: 35V; TaMin_C: -55; TaMax_C: 85; Cap_Case: 1206
C29 = 08053C104KAT2A: CAP, CERM, 0.1uF, 25V, +/-10%, X7R, 0805; Manufacturer: AVX; Polarized: N; CompType: Capacitor; U/M: EA; Cap_F: 0.0000001; Tolerance_%: 10; ESR_Ohm: 0.28; Value1: 0.28 ohm; VDC_V: 25; TaMin_C: -55; TaMax_C: 125; Cap_Case: 0805
C30 C31 = GRM216R71E102KA01D: as C3 on sheet Pg2-Main
C32 C33 = C2012JB1V226M125AC: CAP, CERM, 22uF, 35V, +/-20%, JB, 0805; Manufacturer: TDK; Polarized: N; CompType: Capacitor; U/M: EA; Cap_F: 0.000022; Tolerance_%: 20; Value1: Unknown; VDC_V: 35; TaMin_C: -25; TaMax_C: 85; Cap_Case: 0805
C34 = GMK212B7105KG-T: CAP, CERM, 1uF, 35V, +/-10%, X7R, 0805; Manufacturer: Taiyo Yuden; Polarized: N; CompType: Capacitor; U/M: EA; Cap_F: 0.000001; Tolerance_%: 10; Value1: Unknown; VDC_V: 35; TaMin_C: -55; TaMax_C: 125; Cap_Case: 0805
D2 = 10BQ040TRPBF: Diode, Schottky, 60V, 1A, SMB; Manufacturer: MCC; U/M: EA; Vf_V: 0.72; Value: 60VV; Value2: 0.72V; Io_A: 1; Vr_V: 60; TJmax_C: 150
D3 = 10BQ040TRPBF: Diode, Schottky, 60V, 1A, SMB; Manufacturer: MCC; U/M: EA; Vf_V: 0.72; Value2: 0.72V; Io_A: 1; Vr_V: 60; TJmax_C: 150; RJC_CperW: 36
D4 = 10BQ040TRPBF: Diode, Schottky, 40V, 1A, SMB; Manufacturer: International Rectifier; U/M: EA; Vf_V: 0.53; Value2: 0.53V; Io_A: 1; Vr_V: 40; TJmax_C: 150; RJC_CperW: 36
D6-D8 = LG L29K-G2J1-24-Z: LED, Green, SMD; Manufacturer: OSRAM; Vf_V: 1.7; Value2: 1.7V; Io_A: 0.002; Tjmax_C: 110; Value1: W; U/M: EA
J5 = 282834-2: as J6 on sheet Pg2-Main
R1 R53 R54 = CRCW08051K00FKEA: RES, 1.00 k, 1%, 0.125 W, 0805; Manufacturer: Vishay-Dale; CompType: Resistor; Value: 1.00k; Res_ohm: 1000; Value_Code: 1k00; Tolerance_%: 1; Power_W: 0.125; Value2: 0.125W; VDC_V: 150; TempCo: 100 ppm/C; EIA_Code: E96; U/M: EA
R46 = RT0805BRD07126KL: RES, 126k ohm, 0.1%, 0.125W, 0805; Manufacturer: Yageo America; CompType: Resistor; Res_ohm: 126000; Tolerance_%: 0.1; Power_W: 0.125; VDC_V: 150; TempCo: 25 ppm/C; EIA_Code: E192; U/M: EA
R47 = ERJ-6GEY0R00V: as R30 on sheet Pg2-Main
R48 = RT0805BRD0735K2L: RES, 35.2 k, 0.1%, 0.125 W, 0805; Manufacturer: Yageo America; CompType: Resistor; Value: 35.2k; Res_ohm: 35200; Value_Code: 35k2; Tolerance_%: 0.1; Power_W: 0.125; Value2: 0.125W; VDC_V: 150; TempCo: 25 ppm/C; EIA_Code: E192; U/M: EA
R49 = RT0805BRD07145KL: RES, 145 k, 0.1%, 0.125 W, 0805; Manufacturer: Yageo America; CompType: Resistor; Value: 145k; Res_ohm: 145000; Tolerance_%: 0.1; Power_W: 0.125; Value2: 0.125W; VDC_V: 150; TempCo: 25 ppm/C; EIA_Code: E192; U/M: EA
R50 = CRCW080512K7FKEA: RES, 12.7 k, 1%, 0.125 W, 0805; Manufacturer: Vishay-Dale; CompType: Resistor; Value: 12.7k; Res_ohm: 12700; Value_Code: 12k7; Tolerance_%: 1; Power_W: 0.125; Value2: 0.125W; VDC_V: 150; TempCo: 100 ppm/C; EIA_Code: E96; U/M: EA
R51 = CRCW080519K6FKEA: RES, 19.6 k, 1%, 0.125 W, 0805; Manufacturer: Vishay-Dale; CompType: Resistor; Value: 19.6k; Res_ohm: 19600; Value_Code: 19k6; Tolerance_%: 1; Power_W: 0.125; Value2: 0.125W; VDC_V: 150; TempCo: 100 ppm/C; EIA_Code: E96; U/M: EA
R52 = CRCW080520K0FKEA: RES, 20.0 k, 1%, 0.125 W, 0805; Manufacturer: Vishay-Dale; CompType: Resistor; Value: 20.0k; Res_ohm: 20000; Value_Code: 20k0; Tolerance_%: 1; Power_W: 0.125; Value2: 0.125W; VDC_V: 150; TempCo: 100 ppm/C; EIA_Code: E96; U/M: EA
SW = TP-032_RND: Test Point, O.032 Hole; Manufacturer: STD; Value: STD
T1 = 750342773: Transformer, 60 uH, TH; Manufacturer: Wurth Elektronik eiSos; SymbolCreator: Altium; Value: 60 uH; U/M: EA
U6 = LM5160ADNTR: Wide Input 65V, 1.5A Synchronous Step-Down DC-DC Converter, DNT0012B; Alternate PartNumber: LM5160ADNTT; Manufacturer: Texas Instruments; SymbolCreator: a0411947; CompType: IC; U/M: EA
U7 = TLV1117-50IDRJR: LDO with 6.4 to 15 V Input and 5 V Output, -40 to 125 degC, 8-Pin SON (DRJ), Green (RoHS & no Sb/Br); Manufacturer: Texas Instruments; Alternate Manufacturer: None; Alternate PartNumber: Equivalent; Iout(Max)(A): 0.8; Iq(Typ)(mA): 5; SubFamily: Single Channel LDO; Vin(Max)(V): 15; Vin(Min)(V): 6.4
U8 = LP2985AIM5-5.0: Micropower 150 mA Low-Noise Ultra Low-Dropout Regulator, 5-pin SOT-23; Manufacturer: Texas Instruments; PackageTopMarking: L0UA*XTT; PowerWise: N; CompType: LDO IC

## Sheet Pg4_Hardware_ANSI-B.SchDoc
size 431 x 279 mm; Date: Not shown in title block; ApprovedBy: Not shown in title block; CheckedBy: Not shown in title block; Author: Not shown in title block; CompanyName: Not shown in title block; Engineer: Not shown in title block; Organization: Not shown in title block; Address1: Not shown in title block; Address2: Not shown in title block; Address3: Not shown in title block; Address4: Not shown in title block; DocumentNumber: 5; Revision: Use project parameter SCH_Rev; SheetNumber: 5; SheetTotal: 5; PageSetup: Record=PageOptions|CenterHorizontal=True|CenterVertical=True|PrintScale=1.00|XCorrection=1.00|YCorrection=1.00|PrintKind=0|BorderSize=5000000|LeftOffset=0|BottomOffset=0|Orientation=2|PaperLength=1000|PaperWidth=1000|Scale=100|PaperSource=15|PrintQuality=600|MediaType=1|DitherType=10|PaperKind=Letter|PrintScaleMode=1
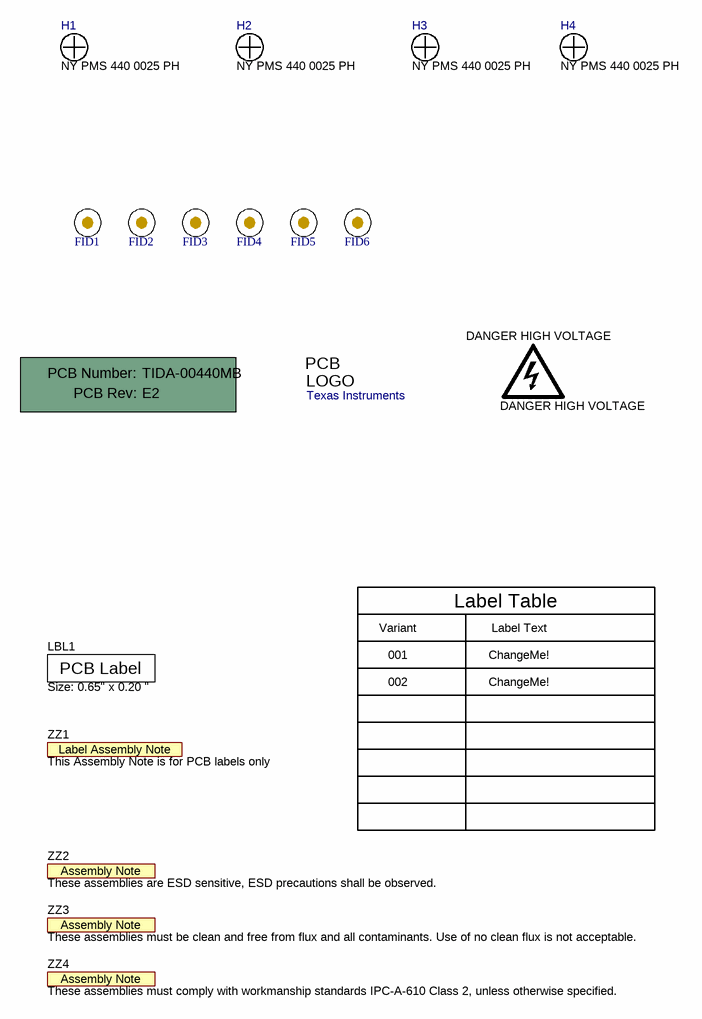
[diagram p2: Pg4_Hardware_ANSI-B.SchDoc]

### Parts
!PCB  Printed Circuit Board  (value not drawn)  (mechanical)
DANGER_HIGH_VOLTAGE  DANGER HIGH VOLTAGE  [IEC_HighVoltage_Large]  (no BOM)
FID1  Fiducial  [Fiducial10-30]  (value not drawn)
FID2  Fiducial  [Fiducial10-30]  (value not drawn)
FID3  Fiducial  [Fiducial10-30]  (value not drawn)
FID4  Fiducial  [Fiducial10-30]  (value not drawn)
FID5  Fiducial  [Fiducial10-30]  (value not drawn)
FID6  Fiducial  [Fiducial10-30]  (value not drawn)
H1  NY PMS 440 0025 PH  [NY PMS 440 0025 PH]
H2  NY PMS 440 0025 PH  [NY PMS 440 0025 PH]
H3  NY PMS 440 0025 PH  [NY PMS 440 0025 PH]
H4  NY PMS 440 0025 PH  [NY PMS 440 0025 PH]
LBL1  Size: 0.65" x 0.20 "  [Label_650x200]
Logo1  Texas Instruments  [TI_Stacked_Overlay_Small]  (no BOM)
ZZ1  This Assembly Note is for PCB labels only  [AssemblyNoteLabel]  (no BOM)
ZZ2  These assemblies are ESD sensitive, ESD precautions shall be observed.  [AssemblyNote]  (no BOM)
ZZ3  These assemblies must be clean and free from flux and all contaminants. Use of no clean flux is not acceptable.  [AssemblyNote]  (no BOM)
ZZ4  These assemblies must comply with workmanship standards IPC-A-610 Class 2, unless otherwise specified.  [AssemblyNote]  (no BOM)

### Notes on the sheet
- Variant
- Label Table
- Label Text
- 001
- 002
- ChangeMe!

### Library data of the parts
!PCB = PCB: Manufacturer: Any; PartNumber: TIDA-00440MB; SymbolCreator: a0412235
DANGER_HIGH_VOLTAGE = IEC_HighVoltage: IEC 61010-1 High Voltage Warning; SymbolCreator: a0412235
FID1-FID6 = Fiducial: Fiducial mark.  There is nothing to buy or mount.; SymbolCreator: codlsc
H1-H4 = NY PMS 440 0025 PH: Machine Screw, Round, #4-40 x 1/4, Nylon, Philips panhead; Manufacturer: B&F Fastener Supply; CompType: Hardware; SymbolCreator: codlsc; U/M: EA
LBL1 = THT-14-423-10: Thermal Transfer Printable Labels, 0.650" W x 0.200" H - 10,000 per roll; Manufacturer: Brady; SymbolCreator: a0412235; CompType: Label
Logo1 = TI_Logo: Texas Instrument Corporate Signature; SymbolCreator: a0412235
ZZ1 = AssemblyNoteLabel: SymbolCreator: a0412235
ZZ2-ZZ4 = AssemblyNote: SymbolCreator: codlsc

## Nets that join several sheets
3V3: Pg2-Main (12 pins), Pg3 (7 pins)
5V_VCC1: Pg2-Main (14 pins), Pg3 (8 pins)
5V_VCC2: Pg2-Main (6 pins), Pg3 (5 pins)
GND: Pg2-Main (13 pins), Pg3 (13 pins)
GND1: Pg2-Main (19 pins), Pg3 (8 pins)
GND2: Pg2-Main (19 pins), Pg3 (9 pins)

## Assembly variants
001: not fitted C15 C35 C42 C43 R30 R31 R32 R37 R38 R39 R40 R42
